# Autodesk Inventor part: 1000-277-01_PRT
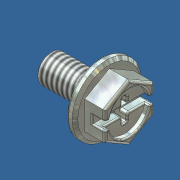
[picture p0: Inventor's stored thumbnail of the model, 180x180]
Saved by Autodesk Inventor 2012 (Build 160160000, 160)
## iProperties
Created: 2007-03
Part Number: 1000-277-01_PRT
Document SubType Name: Modeling
Designer: Andy Moles
Material: Steel
Mass: 5.32321 g
Surface Area: 7.06394 cm^2
Volume: 0.678116 cm^3
Density: 7.85 g/cm^3
Author: Andy Moles
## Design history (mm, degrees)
feature "Base1"
thread "Thread1" dims "d0" = 10, "d1" = 0
body "Solid1"
